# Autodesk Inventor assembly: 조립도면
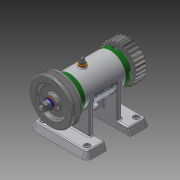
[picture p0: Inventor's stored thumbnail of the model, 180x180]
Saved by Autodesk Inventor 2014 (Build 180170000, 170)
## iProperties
Created: 2016-07
Part Number: 조립도면
Document SubType Name: Assembly
Designer: USER
Author: USER
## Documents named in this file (16)
- C:\Users\USER\Desktop\460707V1026\조립도면.iam
- C:\Users\USER\Desktop\460707V1026\본체.ipt
- C:\Users\USER\Desktop\460707V1026\키 3 x 3 x 12.ipt
- C:\Users\USER\Desktop\460707V1026\볼트 M 6 x 8.ipt
- C:\Users\USER\Desktop\460707V1026\볼트 M4 x 12.ipt
- C:\Users\USER\Desktop\460707V1026\스퍼기어.ipt
- C:\Users\USER\Desktop\460707V1026\스프링와셔 8.ipt
- C:\Users\USER\Desktop\460707V1026\오일 실 15 25 7.ipt
- C:\Users\USER\Desktop\460707V1026\와셔 6x11.5.ipt
- C:\Users\USER\Desktop\460707V1026\와셔 8x17.ipt
- C:\Users\USER\Desktop\460707V1026\축.ipt
- C:\Users\USER\Desktop\460707V1026\커버.ipt
- C:\Users\USER\Desktop\460707V1026\베어링 15 x 32 x 9.ipt
- C:\Users\USER\Desktop\460707V1026\V벨트풀리.ipt
- C:\Users\USER\Desktop\460707V1026\너트 M 8.ipt
- C:\Users\USER\Desktop\460707V1026\니플 M 6 x 0.75.ipt
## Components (11 placed, 3 different names)
1. KS B 2023 6002 - 15 x 32 x 9:1
2. V벨트풀리:1
3. KS B 2023 6002 - 15 x 32 x 9:2
4. ISO 4762 M4 x 12:1
5. ISO 4762 M4 x 12:3
6. ISO 4762 M4 x 12:4
7. ISO 4762 M4 x 12:5
8. ISO 4762 M4 x 12:2
9. ISO 4762 M4 x 12:6
10. ISO 4762 M4 x 12:7
11. ISO 4762 M4 x 12:8
